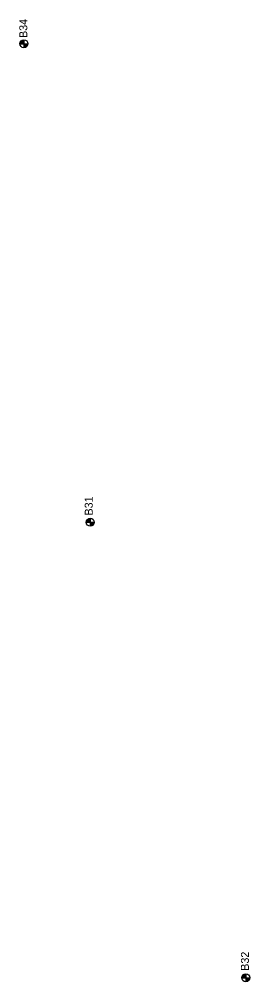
# Model space of a CAD drawing. Extents: x 345549 to 379569, y 127949 to 230467.
# Drawn here: x 361660 to 361949, y 145719 to 146922 of the extents above; entities that cross this region are included whole.
import ezdxf

# ---------------------------------------------------------------- set-up
doc = ezdxf.new("R2010")
doc.units = 0
for name, color, linetype in [('E_SOIL_BORE1 [KAPUR_CADDS_LEVELS]', 7, 'Continuous'), ('E_SOIL_BORE2 [KAPUR_CADDS_LEVELS]', 7, 'Continuous'), ('P_MARK', 7, 'Continuous')]:
    doc.layers.add(name, color=color, linetype=linetype)

msp = doc.modelspace()

# ---------------------------------------------------------------- linework, layer by layer
at = {"layer": 'P_MARK'}
for p, q in [((361665.8, 146896.4), (361665.8, 146886.4)), ((361660.8, 146891.4), (361670.8, 146891.4)), ((361748.9, 146298.4), (361748.9, 146288.4)), ((361743.9, 146293.4), (361753.9, 146293.4)), ((361938.7, 145724.1), (361948.7, 145724.1)), ((361943.7, 145729.1), (361943.7, 145719.1))]:
    msp.add_line(p, q, dxfattribs=at)
for centre in [(361665.8, 146891.4), (361748.9, 146293.4), (361943.7, 145724.1)]:
    msp.add_circle(centre, 5, dxfattribs=at)
for centre, radius, start, end in [((361665.8, 146891.4), 4.5, 89.9869, 179.9869), ((361665.8, 146891.4), 4, 89.9869, 179.9869), ((361665.8, 146891.4), 3.5, 89.9869, 179.9869), ((361665.8, 146891.4), 3, 89.9869, 179.9869), ((361665.8, 146891.4), 2.5, 89.9869, 179.9869), ((361665.8, 146891.4), 2, 89.9869, 179.9869), ((361665.8, 146891.4), 1.5, 89.9869, 179.9869), ((361665.8, 146891.4), 1, 89.9869, 179.9869), ((361665.8, 146891.4), 0.5, 89.9869, 179.9869), ((361665.8, 146891.4), 4.5, 269.9869, 359.9869), ((361665.8, 146891.4), 4, 269.9869, 359.9869), ((361665.8, 146891.4), 3.5, 269.9869, 359.9869), ((361665.8, 146891.4), 3, 269.9869, 359.9869), ((361665.8, 146891.4), 2.5, 269.9869, 359.9869), ((361665.8, 146891.4), 2, 269.9869, 359.9869), ((361665.8, 146891.4), 1.5, 269.9869, 359.9869), ((361665.8, 146891.4), 1, 269.9869, 359.9869), ((361665.8, 146891.4), 0.5, 269.9869, 359.9869), ((361748.9, 146293.4), 4.5, 89.9869, 179.9869), ((361748.9, 146293.4), 4, 89.9869, 179.9869), ((361748.9, 146293.4), 3.5, 89.9869, 179.9869), ((361748.9, 146293.4), 3, 89.9869, 179.9869), ((361748.9, 146293.4), 2.5, 89.9869, 179.9869), ((361748.9, 146293.4), 2, 89.9869, 179.9869), ((361748.9, 146293.4), 1.5, 89.9869, 179.9869), ((361748.9, 146293.4), 1, 89.9869, 179.9869), ((361748.9, 146293.4), 0.5, 89.9869, 179.9869), ((361748.9, 146293.4), 4.5, 269.9869, 359.9869), ((361748.9, 146293.4), 4, 269.9869, 359.9869), ((361748.9, 146293.4), 3.5, 269.9869, 359.9869), ((361748.9, 146293.4), 3, 269.9869, 359.9869), ((361748.9, 146293.4), 2.5, 269.9869, 359.9869), ((361748.9, 146293.4), 2, 269.9869, 359.9869), ((361748.9, 146293.4), 1.5, 269.9869, 359.9869), ((361748.9, 146293.4), 1, 269.9869, 359.9869), ((361748.9, 146293.4), 0.5, 269.9869, 359.9869), ((361943.7, 145724.1), 4.5, 89.9869, 179.9869), ((361943.7, 145724.1), 4, 89.9869, 179.9869), ((361943.7, 145724.1), 3.5, 89.9869, 179.9869), ((361943.7, 145724.1), 3, 89.9869, 179.9869), ((361943.7, 145724.1), 2.5, 89.9869, 179.9869), ((361943.7, 145724.1), 2, 89.9869, 179.9869), ((361943.7, 145724.1), 1.5, 89.9869, 179.9869), ((361943.7, 145724.1), 1, 89.9869, 179.9869), ((361943.7, 145724.1), 0.5, 89.9869, 179.9869), ((361943.7, 145724.1), 4.5, 269.9869, 359.9869), ((361943.7, 145724.1), 4, 269.9869, 359.9869), ((361943.7, 145724.1), 3.5, 269.9869, 359.9869), ((361943.7, 145724.1), 3, 269.9869, 359.9869), ((361943.7, 145724.1), 2.5, 269.9869, 359.9869), ((361943.7, 145724.1), 2, 269.9869, 359.9869), ((361943.7, 145724.1), 1.5, 269.9869, 359.9869), ((361943.7, 145724.1), 1, 269.9869, 359.9869), ((361943.7, 145724.1), 0.5, 269.9869, 359.9869)]:
    msp.add_arc(centre, radius, start, end, dxfattribs=at)

# ---------------------------------------------------------------- texts
at = {"layer": 'E_SOIL_BORE1 [KAPUR_CADDS_LEVELS]'}
msp.add_text('B34', height=10, rotation=89.9869, dxfattribs=at).set_placement((361670.1, 146898.6))
at = {"layer": 'E_SOIL_BORE2 [KAPUR_CADDS_LEVELS]'}
for s, p in [('B31', (361752, 146301.8)), ('B32', (361947.6, 145732.9))]:
    msp.add_text(s, height=10, rotation=89.9869, dxfattribs=at).set_placement(p)

doc.saveas('drawing.dxf')
